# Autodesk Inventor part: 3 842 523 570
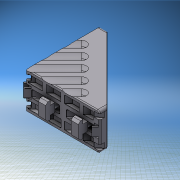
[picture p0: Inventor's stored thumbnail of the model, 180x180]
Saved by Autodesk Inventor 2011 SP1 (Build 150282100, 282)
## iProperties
Created: 2011-02
Part Number: 3 842 523 570
Description: GUSSET 45X90 W/FASTNR 10-10MM
Document SubType Name: Modeling
Designer: SRW
Stock Number: 3 842 523 570
Density: 2.71 g/cm^3
Material: Aluminum-6061
Mass: 215.523 g
Surface Area: 365.103 cm^2
Volume: 79.5289 cm^3
Author: SRW
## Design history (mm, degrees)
feature "Base1"
body "Solid1"
